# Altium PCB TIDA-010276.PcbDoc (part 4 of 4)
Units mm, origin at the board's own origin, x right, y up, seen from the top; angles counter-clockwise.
Board outline 146.48 x 90.27 mm, 4 copper layers (Top Layer, Signal Layer1, Signal Layer2, Bottom Layer), stack 1.631 mm thick; 271 components, 98 nets, 671 pads, 1828 vias.
Unrouted connection lines stored in the file: 2.
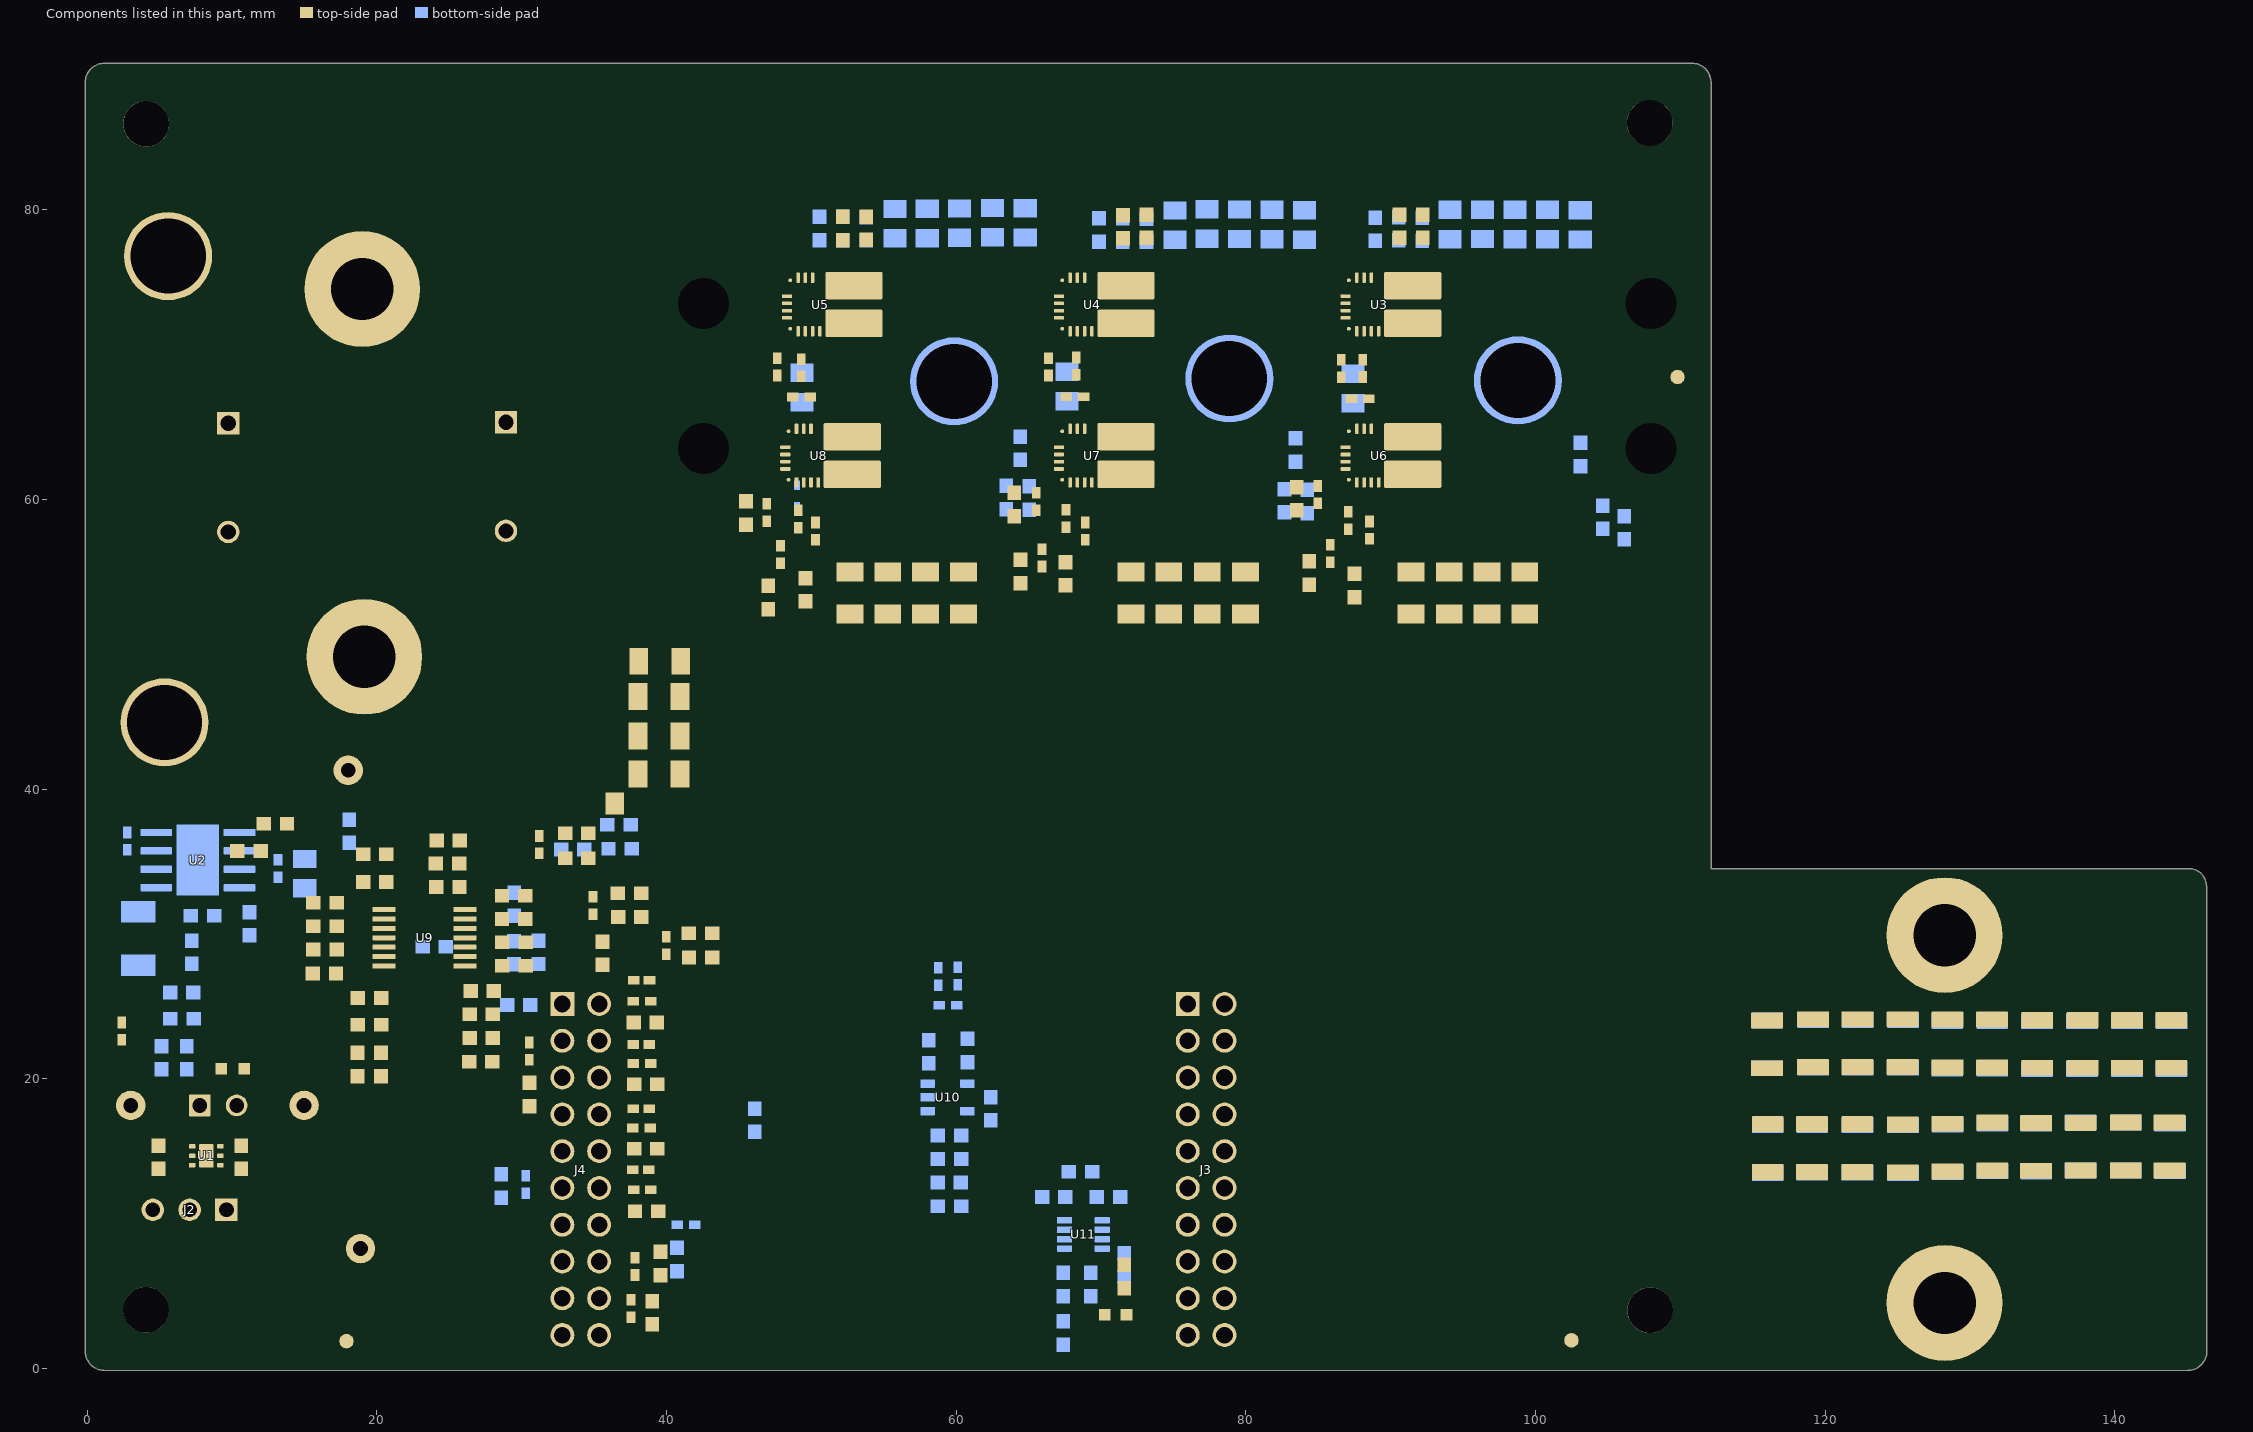
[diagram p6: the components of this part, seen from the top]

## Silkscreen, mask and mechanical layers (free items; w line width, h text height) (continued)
Drill Drawing:
  circle w0.254: c131.689,110.883 r0.702
  circle w0.254: c131.689,85.621 r0.421
  circle w0.254: c131.689,85.621 r0.702
  lines w0.254: 130.987,83.165 132.391,83.165 131.689,81.762 130.987,83.165 ; 130.987,88.428 131.338,88.428 131.689,88.077 132.04,88.428 132.391,88.428 132.04,88.779 132.391,89.13 132.04,89.13 131.689,89.481 131.338,89.13 130.987,89.13 131.338,88.779 130.987,88.428 ; 130.987,91.586 131.338,91.586 131.338,91.235 132.04,91.235 132.04,91.586 132.391,91.586 132.391,92.288 132.04,92.288 132.04,92.638 131.338,92.638 131.338,92.288 130.987,92.288 130.987,91.586 ; 130.987,94.393 132.391,94.393 132.391,95.796 130.987,95.796 130.987,94.393 ; 130.987,97.55 131.689,97.901 132.391,97.55 132.04,98.252 132.391,98.954 131.689,98.603 130.987,98.954 131.338,98.252 130.987,97.55 ; 130.987,101.059 131.338,101.059 131.689,100.708 132.04,101.059 132.391,101.059 132.04,101.41 132.391,101.761 132.04,101.761 131.689,102.112 131.338,101.761 130.987,101.761 131.338,101.41 130.987,101.059 ; 130.987,105.269 132.391,105.269 131.689,103.866 130.987,105.269 ; 130.987,107.024 130.987,107.375 131.338,107.725 130.987,108.076 130.987,108.427 131.338,108.427 131.689,108.076 132.04,108.427 132.391,108.427 132.391,108.076 132.04,107.725 132.391,107.375 132.391,107.024 132.04,107.024 131.689,107.375 131.338,107.024 130.987,107.024 ; 130.987,113.339 132.391,113.339 132.391,114.743 130.987,114.743 130.987,113.339 ; 131.268,82.885 132.11,82.885 131.689,82.043 131.268,82.885 ; 131.268,97.831 131.689,98.042 132.11,97.831 131.899,98.252 132.11,98.673 131.689,98.463 131.268,98.673 131.478,98.252 131.268,97.831 ; 131.268,101.199 131.478,101.199 131.689,100.989 131.899,101.199 132.11,101.199 131.899,101.41 132.11,101.62 131.899,101.62 131.689,101.831 131.478,101.62 131.268,101.62 131.478,101.41 131.268,101.199 ; 131.268,113.62 132.11,113.62 132.11,114.462 131.268,114.462 131.268,113.62
  lines w0.305: 129.715,80.815 211.795,80.815 ; 129.715,115.55 211.795,115.55 ; 138.297,77.657 138.297,118.707 ; 146.729,77.657 146.729,118.707 ; 162.898,77.657 162.898,118.707 ; 169.48,77.657 169.48,118.707 ; 179.009,77.657 179.009,118.707 ; 197.407,77.657 197.407,118.707 ; 129.715,77.657 211.795,77.657 211.795,118.707 129.715,118.707 129.715,77.657
  text "Symbol" at 131.61,116.497 h1.83
  text "Quantity" at 139.244,116.497 h1.83
  text "Finished Hole Size" at 147.677,116.497 h1.83
  text "Plated" at 163.845,116.497 h1.83
  text "Hole Type" at 170.428,116.497 h1.83
  text "Drill Layer Pair" at 179.957,116.497 h1.83
  text "Hole Tolerance" at 198.355,116.497 h1.83
  text "4" at 139.244,113.339 h1.52
  text "124.02mil (3.150mm)" at 147.677,113.339 h1.52
  text "NPTH" at 163.845,113.339 h1.52
  text "Round" at 170.428,113.339 h1.52
  text "Top Layer - Bottom Layer" at 179.957,113.339 h1.52
  text "5" at 139.244,110.181 h1.52
  text "204.72mil (5.200mm)" at 147.677,110.181 h1.52
  text "NPTH" at 163.845,110.181 h1.52
  text "Round" at 170.428,110.181 h1.52
  text "Top Layer - Bottom Layer" at 179.957,110.181 h1.52
  text "1797" at 139.244,107.024 h1.52
  text "7.87mil (0.200mm)" at 147.677,107.024 h1.52
  text "PTH" at 163.845,107.024 h1.52
  text "Round" at 170.428,107.024 h1.52
  text "Top Layer - Bottom Layer" at 179.957,107.024 h1.52
  text "6" at 139.244,103.866 h1.52
  text "12.99mil (0.330mm)" at 147.677,103.866 h1.52
  text "PTH" at 163.845,103.866 h1.52
  text "Round" at 170.428,103.866 h1.52
  text "Top Layer - Bottom Layer" at 179.957,103.866 h1.52
  text "24" at 139.244,100.708 h1.52
  text "19.69mil (0.500mm)" at 147.677,100.708 h1.52
  text "PTH" at 163.845,100.708 h1.52
  text "Round" at 170.428,100.708 h1.52
  text "Top Layer - Bottom Layer" at 179.957,100.708 h1.52
  text "1" at 139.244,97.55 h1.52
  text "31.50mil (0.800mm)" at 147.677,97.55 h1.52
  text "PTH" at 163.845,97.55 h1.52
  text "Round" at 170.428,97.55 h1.52
  text "Top Layer - Bottom Layer" at 179.957,97.55 h1.52
  text "9" at 139.244,94.393 h1.52
  text "40.00mil (1.016mm)" at 147.677,94.393 h1.52
  text "PTH" at 163.845,94.393 h1.52
  text "Round" at 170.428,94.393 h1.52
  text "Top Layer - Bottom Layer" at 179.957,94.393 h1.52
  text "4" at 139.244,91.235 h1.52
  text "41.34mil (1.050mm)" at 147.677,91.235 h1.52
  text "PTH" at 163.845,91.235 h1.52
  text "Round" at 170.428,91.235 h1.52
  text "Top Layer - Bottom Layer" at 179.957,91.235 h1.52
  text "40" at 139.244,88.077 h1.52
  text "45.28mil (1.150mm)" at 147.677,88.077 h1.52
  text "PTH" at 163.845,88.077 h1.52
  text "Round" at 170.428,88.077 h1.52
  text "Top Layer - Bottom Layer" at 179.957,88.077 h1.52
  text "4" at 139.244,84.92 h1.52
  text "137.79mil (3.500mm)" at 147.677,84.92 h1.52
  text "PTH" at 163.845,84.92 h1.52
  text "Round" at 170.428,84.92 h1.52
  text "Top Layer - Bottom Layer" at 179.957,84.92 h1.52
  text "4" at 139.244,81.762 h1.52
  text "169.29mil (4.300mm)" at 147.677,81.762 h1.52
  text "PTH" at 163.845,81.762 h1.52
  text "Round" at 170.428,81.762 h1.52
  text "Top Layer - Bottom Layer" at 179.957,81.762 h1.52
  text "1898 Total" at 139.244,78.604 h1.52
  text ".Layer_Name" at -51.844,-91.306 h1.52
M17 Embedded Cavity:
  text ".Layer_Name" at -51.844,-91.306 h1.52
M18 Embedded Assembly:
  text ".Layer_Name" at -51.844,-91.306 h1.52
M19 Embedded Keepout:
  text ".Layer_Name" at -51.59,-91.052 h1.52

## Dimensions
39.264,51.48 to 39.264,81.459 on M2 Board Dimensions
111.299,51.48 to 39.264,51.48 on M2 Board Dimensions
107.987,73.535 to 111.299,81.445 on M2 Board Dimensions
107.987,73.535 to 111.299,81.445 on M2 Board Dimensions
111.299,51.48 to 107.986,63.527 on M2 Board Dimensions
111.299,51.48 to 107.986,63.527 on M2 Board Dimensions
42.561,63.529 to 39.264,51.48 on M2 Board Dimensions
39.264,51.48 to 42.561,63.529 on M2 Board Dimensions
42.564,73.537 to 39.264,81.459 on M2 Board Dimensions
39.264,81.459 to 42.564,73.537 on M2 Board Dimensions
112,-0.174 to 0,0 on M2 Board Dimensions
-66.5,-79.66 to -41.1,-79.66 on M2 Board Dimensions
0,0 to 0.001,90 on M2 Board Dimensions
